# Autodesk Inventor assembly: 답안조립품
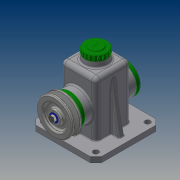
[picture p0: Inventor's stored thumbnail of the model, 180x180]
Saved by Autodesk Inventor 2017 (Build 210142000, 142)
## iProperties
Part Number: 답안조립품
Material: 일반
Document SubType Name: Assembly
Designer: 20
Author: 20
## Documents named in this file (14)
- C:\Users\20\Desktop\470818V1003\답안조립품.iam
- C:\Users\20\Desktop\470818V1003\본체.ipt
- C:\Users\20\Desktop\470818V1003\뒤커버.ipt
- C:\Users\20\Desktop\470818V1003\앞커버.ipt
- C:\Users\20\Desktop\470818V1003\상부캡.ipt
- C:\Users\20\Desktop\470818V1003\멈춤링 15 x 1.ipt
- C:\Users\20\Desktop\470818V1003\베어링 15 x 35 x 11.ipt
- C:\Users\20\Desktop\470818V1003\축.ipt
- C:\Users\20\Desktop\470818V1003\키 5 x 5 x 14.ipt
- C:\Users\20\Desktop\470818V1003\오일실 15 25 7.ipt
- C:\Users\20\Desktop\470818V1003\V-벨트풀리.ipt
- C:\Users\20\Desktop\470818V1003\와셔.ipt
- C:\Users\20\Desktop\470818V1003\볼트 M6 x 12.ipt
- C:\Users\20\Desktop\470818V1003\볼트 M4 x 10.ipt
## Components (1 placed, 1 different names)
1. V-벨트풀리:1 — 플러쉬:1
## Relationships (1: Flush 1)
- 플러쉬:1 [Flush]: V-벨트풀리:1
